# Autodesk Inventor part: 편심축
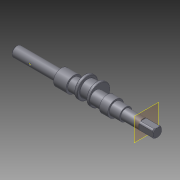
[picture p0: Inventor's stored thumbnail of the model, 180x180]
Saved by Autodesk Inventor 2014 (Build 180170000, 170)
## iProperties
Company: 한국ATC센터
Created: 2015-12
Part Number: 편심축
Document SubType Name: Modeling
Designer: mdu
Density: 7.86 g/cm^3
Mass: 248.518 g
Surface Area: 94.9962 cm^2
Volume: 31.6181 cm^3
Material: 강철, 연강
Appearance: 강철
Author: mdu
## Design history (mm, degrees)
sketch "스케치1"
  geometry: L1 (-84.5, 0)-(84.5, 0); L2 (-84.5, 0)-(-84.5, 6); L3 (-84.5, 6)-(-30.5, 6); L4 (-30.5, 6)-(-30.5, 9.5); L5 (-30.5, 9.5)-(-15.5, 9.5); L6 (-15.5, 9.5)-(-15.5, 7.5); L7 (-15.5, 7.5)-(46.5, 7.5); L8 (84.5, 6)-(84.5, 0); L9 (34.5, 7.5)-(34.5, 9.5); L10 (34.5, 9.5)-(24.5, 9.5); L11 (24.5, 9.5)-(24.5, 7.5); L12 (46.5, 7.5)-(46.5, 6); L13 (46.5, 6)-(84.5, 6); 2 further points
  constraints: 26 end point, 6 parallel, 6 perpendicular, 2 point on line, 1 coincident, 1 horizontal, 1 midpoint
  dimensions: "d1" = 12 diameter of L3 L1; "d2" = 15 diameter of L7 L1; "d4" = 15 distance of L4.end L5.end; "d5" = 19 diameter of L5 L1; "d24" = 10 distance of L9.end L10.end; "d25" = 19 diameter of L10 L1; "d27" = 40 distance between parallel lines of L11 L6; "d28" = 54 distance of L2.end L3.end; "d29" = 50 distance between parallel lines of L8 L9; "d41" = 38 distance between parallel lines of L8 L12; "d42" = 12 diameter of L13 L1
revolve "회전1" stored, may be unused: angle "d6" = 90 deg
node "작업 평면1"
sketch "스케치2"
  geometry: C1 r 7.5 at (0, 0) reference; C2 r 12.5 at (0, 4.5); 1 further point
  constraints: 1 centre point, 1 vertical alignment
  dimensions: "d8" = 4.5 distance of point (0, 0) C2.centre; "d9" = 25 diameter of C2
extrude "돌출1" join sketch "스케치2" distance "d10" = 18; taper "d11" = 0 deg
chamfer "모따기1" distance "d12" = 1; stored, may be unused: second distance "d13" = 2, angle "d14" = 45 deg
chamfer "모따기2" distance "d15" = 0.5; stored, may be unused: second distance "d16" = 2, angle "d17" = 45 deg
node "작업 평면2"
sketch "스케치3"
  geometry: L1 (4, -2)-(18, -2); L2 (18, 2)-(4, 2); L3 (27, 5)-(27, -5) reference; A1 r 2 centre (18, 0) between (18, -2) and (18, 2); A2 r 2 centre (4, 0) between (4, 2) and (4, -2); 2 further points
  constraints: 4 end point, 4 point on circle, 4 tangent, 2 centre point, 1 horizontal, 1 horizontal alignment, 1 midpoint, 1 parallel
  dimensions: "d18" = 7 distance edge to line of A1 L3; "d19" = 4 distance between parallel lines of L2 L1; "d20" = 18 dimension on A1 A2
extrude "돌출2" cut sketch "스케치3" distance "d21" = 2.5; taper "d22" = 0 deg
revolve "회전2" stored, may be unused: angle "d26" = 90 deg
node "작업 평면3"
sketch "스케치10"
  geometry: L1 (-5, -5)-(5, -5); L2 (5, -5)-(5, 5); L3 (5, 5)-(-5, 5); L4 (-5, 5)-(-5, -5); L5 (-5, -5)-(5, 5); L6 (5, -5)-(-5, 5); C1 r 5 at (0, 0) reference; C2 r 6 at (0, 0) reference; A1 r 6 centre (0, 0) between (5, 3.317) and (3.317, 5); A2 r 6 centre (0, 0) between (5, -3.317) and (5, 3.317); A3 r 6 centre (0, 0) between (3.317, -5) and (5, -3.317); A4 r 6 centre (0, 0) between (-3.317, -5) and (3.317, -5); A5 r 6 centre (0, 0) between (-5, -3.317) and (-3.317, -5); A6 r 6 centre (0, 0) between (-5, 3.317) and (-5, -3.317); A7 r 6 centre (0, 0) between (-3.317, 5) and (-5, 3.317); A8 r 6 centre (0, 0) between (3.317, 5) and (-3.317, 5)
  constraints: 16 point on circle, 12 end point, 8 centre point, 8 point on line, 2 midpoint, 2 parallel, 2 tangent, 1 coincident, 1 concentric, 1 horizontal, 1 perpendicular
extrude "돌출4" cut sketch "스케치10" distance "d55" = 17; taper "d56" = 0 deg
sketch "스케치6"
  geometry: L1 (-83.5, -6)-(-30.5, -6) reference; L2 (-84.5, -5)-(-84.5, 5) reference; L3 (-83.5, 6)-(-30.5, 6) reference; L4 (-62.5, 6)-(-62.5, -6); L5 (-62.5, -6)-(-61, -6); L6 (-62.5, -4.5)-(-61, -6); L7 (-62.5, -6)-(-62.5, -4.5); 2 further points
  constraints: 8 end point, 4 point on line, 2 perpendicular, 1 coincident
  dimensions: "d43" = 22 distance between parallel lines of L4 L2; "d44" = 45 deg angle of L6 L7; "d45" = 3 diameter of L5.end L4
revolve "회전3" stored, may be unused: angle "d46" = 90 deg
node "작업점1"
node "작업 평면5"
sketch "스케치11"
  geometry: C1 r 12.5 at (0, 0) reference; C2 r 9.5 at (0, 0); 1 further point
  constraints: 1 centre point
  dimensions: "d57" = 3 radial gap between concentric circles of C1 C2
extrude "돌출5" cut sketch "스케치11" stored distance "d58" = 11; taper "d59" = 0 deg
fillet "모깎기1" dims "d60" = 0.3
chamfer "모따기4" distance "d61" = 0.5; stored, may be unused: second distance "d62" = 2, angle "d63" = 45 deg
node "작업 평면6"
node "솔리드1"
node "절단 모서리 투영2"
other parameters: "d7" = 8.5
